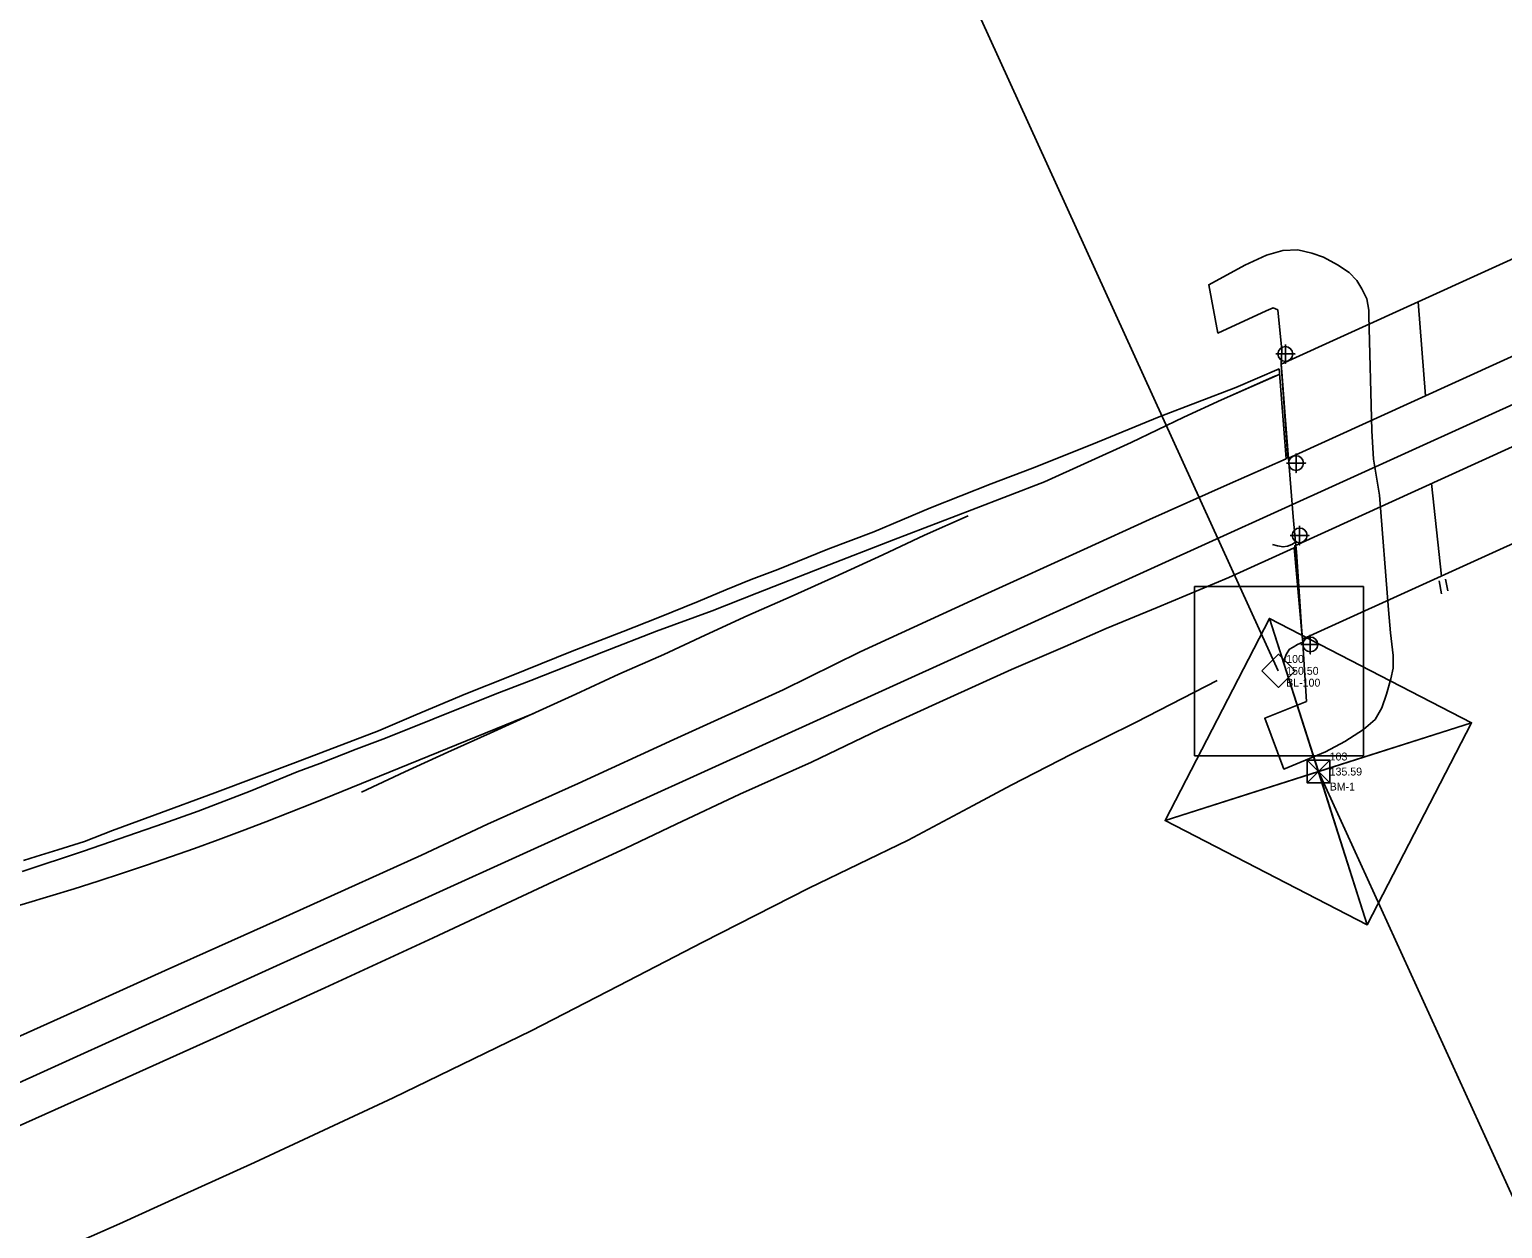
# Model space of a CAD drawing. Extents: x 2243531 to 2252747, y 658714 to 667210.
# Drawn here: x 2248509.1 to 2248974.4, y 663115.4 to 663494.4 of the extents above; entities that cross this region are included whole.
import ezdxf

# ---------------------------------------------------------------- set-up
doc = ezdxf.new("R2010")
doc.units = 0
for name, color, linetype in [('CTL Bench Mark CELL', 7, 'Continuous'), ('CTL Bench Mark Cogo Comment', 7, 'Continuous'), ('CTL Bench Mark Cogo Elevation', 7, 'Continuous'), ('CTL Bench Mark Cogo Number', 7, 'Continuous'), ('CTL NGS Horizontal CELL', 7, 'Continuous'), ('CTL Supplemental Horizontal and Vertical CELL', 7, 'Continuous'), ('CTL Supplemental Horizontal and Vertical Cogo Comment', 7, 'Continuous'), ('CTL Supplemental Horizontal and Vertical Cogo Elevation', 7, 'Continuous'), ('CTL Supplemental Horizontal and Vertical Cogo Number', 7, 'Continuous'), ('Exist DTM Regular Point CELL', 7, 'Continuous'), ('Exist Other Culture Area Outline', 7, 'Continuous'), ('Exist Roads Curbs', 7, 'Continuous'), ('Exist Roads EOP', 7, 'Continuous'), ('Exist Roads EOT', 7, 'Continuous'), ('Exist Structure Major Bridge Seam', 7, 'Continuous'), ('Exist Structure Major Bridge WW', 7, 'Continuous'), ('Exist Structure Major Deck Tunnel Box Culvert', 7, 'Continuous'), ('Prop Horizontal Alignment', 7, 'Continuous')]:
    doc.layers.add(name, color=color, linetype=linetype)

# ---------------------------------------------------------------- blocks, each defined once
blk = doc.blocks.new('CTL BENCH MARK')
at = {"layer": 'CTL Bench Mark CELL'}
blk.add_line((0, 0), (0, 0), dxfattribs=at)
blk.add_lwpolyline([(-0.072, 0.07175), (0.07175, 0.07175), (0.07175, -0.072), (-0.072, -0.072)], close=True, dxfattribs=at)
for points in [[(0.07175, 0.07175), (-0.072, -0.072), (-0.000125, -0.000125), (0.07175, -0.072), (-0.072, 0.07175)], [(-0.000125, -0.000125), (0.07175, 0.07175), (-0.072, 0.07175), (-0.000125, -0.000125)], [(-0.000125, -0.000125), (-0.072, -0.072), (0.07175, -0.072), (-0.000125, -0.000125)]]:
    blk.add_lwpolyline(points, dxfattribs=at)

msp = doc.modelspace()

# ---------------------------------------------------------------- linework, layer by layer
at = {"layer": 'CTL Bench Mark CELL'}
msp.add_line((2248916.28, 663259.84), (2248916.28, 663259.84), dxfattribs=at)
msp.add_line((2248916.28, 663259.84), (2248916.28, 663259.84), dxfattribs=at)
for points in [[(2248900.74, 663308.23), (2248964.61, 663275.27), (2248931.65, 663211.4), (2248867.78, 663244.36)], [(2248912.68, 663263.43), (2248919.87, 663263.43), (2248919.87, 663256.24), (2248912.68, 663256.24)]]:
    msp.add_lwpolyline(points, close=True, dxfattribs=at)
for points in [[(2248964.61, 663275.27), (2248867.78, 663244.36), (2248916.2, 663259.81), (2248931.65, 663211.4), (2248900.74, 663308.23)], [(2248916.2, 663259.81), (2248964.61, 663275.27), (2248900.74, 663308.23), (2248916.2, 663259.81)], [(2248916.2, 663259.81), (2248867.78, 663244.36), (2248931.65, 663211.4), (2248916.2, 663259.81)], [(2248919.87, 663263.43), (2248912.68, 663256.24), (2248916.27, 663259.83), (2248919.87, 663256.24), (2248912.68, 663263.43)], [(2248916.27, 663259.83), (2248919.87, 663263.43), (2248912.68, 663263.43), (2248916.27, 663259.83)], [(2248916.27, 663259.83), (2248912.68, 663256.24), (2248919.87, 663256.24), (2248916.27, 663259.83)]]:
    msp.add_lwpolyline(points, dxfattribs=at)
at = {"layer": 'CTL NGS Horizontal CELL'}
for p, q in [((2248903.54, 663291.68), (2248695.02, 663749.27)), ((2248916.28, 663259.84), (2249179.71, 662681.73))]:
    msp.add_line(p, q, dxfattribs=at)
at = {"layer": 'CTL Supplemental Horizontal and Vertical CELL'}
msp.add_line((2248903.54, 663291.68), (2248903.54, 663291.68), dxfattribs=at)
msp.add_line((2248903.54, 663291.68), (2248903.54, 663291.68), dxfattribs=at)
msp.add_line((2248903.54, 663291.68), (2248903.54, 663291.68), dxfattribs=at)
for points in [[(2248877.08, 663318.32), (2248930.45, 663318.32), (2248930.45, 663264.86), (2248877.08, 663264.86)], [(2248898.33, 663291.69), (2248903.57, 663296.94), (2248908.82, 663291.69), (2248903.58, 663286.44)], [(2248898.33, 663291.69), (2248903.57, 663296.94), (2248908.82, 663291.69), (2248903.58, 663286.44)]]:
    msp.add_lwpolyline(points, close=True, dxfattribs=at)
at = {"layer": 'Exist DTM Regular Point CELL'}
for points in [[(2248905.77, 663394.82), (2248905.77, 663388.82), (2248905.77, 663391.82), (2248908.77, 663391.82), (2248902.77, 663391.82)], [(2248909.15, 663360.33), (2248909.15, 663354.33), (2248909.15, 663357.33), (2248912.15, 663357.33), (2248906.15, 663357.33)], [(2248910.28, 663337.47), (2248910.28, 663331.47), (2248910.28, 663334.47), (2248913.28, 663334.47), (2248907.28, 663334.47)], [(2248913.64, 663303.01), (2248913.64, 663297.01), (2248913.64, 663300.01), (2248916.64, 663300.01), (2248910.64, 663300.01)]]:
    msp.add_lwpolyline(points, dxfattribs=at)
for centre in [(2248905.77, 663391.82), (2248909.15, 663357.33), (2248910.28, 663334.47), (2248913.64, 663300.01)]:
    msp.add_circle(centre, 2.34, dxfattribs=at)
at = {"layer": 'Exist Other Culture Area Outline'}
for points in [[(2248932.18, 663403.99), (2248932.14, 663405.62), (2248931.49, 663409.29), (2248929.9, 663412.43), (2248928.34, 663415.09), (2248925.9, 663417.6), (2248922.27, 663419.95), (2248917.85, 663422.38), (2248914.11, 663423.67), (2248909.76, 663424.73), (2248904.97, 663424.53), (2248899.8, 663423.06), (2248892.99, 663419.86), (2248881.57, 663413.68), (2248884.47, 663398.41), (2248899.76, 663405.47), (2248901.94, 663406.43), (2248903.35, 663405.81)], [(2248938.38, 663310.98), (2248935.46, 663347.18), (2248933.61, 663358.61), (2248933.11, 663367.48), (2248932.18, 663403.99)], [(2248954.34, 663320.17), (2248955.09, 663316.04)], [(2248956.31, 663320.64), (2248957.06, 663316.97)], [(2248912.46, 663281.95), (2248899.24, 663276.71), (2248905.32, 663260.64), (2248918.45, 663266.11), (2248924.52, 663269.35), (2248930.43, 663273.17), (2248934.13, 663276.29), (2248936.21, 663279.96), (2248937.74, 663284.28), (2248939.05, 663289.18), (2248939.87, 663292.53), (2248939.87, 663296.53), (2248938.96, 663303.71), (2248938.38, 663310.98)]]:
    msp.add_lwpolyline(points, dxfattribs=at)
at = {"layer": 'Exist Roads Curbs'}
for points in [[(2248909.02, 663332.34), (2248907.81, 663331.63), (2248906.43, 663331.04), (2248905.04, 663330.86), (2248903.25, 663331.16), (2248901.73, 663331.62)], [(2248911.26, 663300.74), (2248909.61, 663299.97), (2248908.19, 663299.14), (2248907.1, 663298.49), (2248906.1, 663297.04), (2248905.58, 663295.64), (2248905.55, 663294.41)]]:
    msp.add_lwpolyline(points, dxfattribs=at)
at = {"layer": 'Exist Roads EOP'}
for points in [[(2248903.84, 663387.13), (2248890.15, 663381.25), (2248865.93, 663371.91), (2248844.61, 663363.25), (2248825.94, 663355.73), (2248812.82, 663350.75), (2248793.66, 663343.19), (2248775.83, 663335.58), (2248761.3, 663330.1), (2248745.45, 663323.7), (2248737.08, 663320.59), (2248729.03, 663317.27), (2248720.32, 663313.59), (2248707.58, 663308.39), (2248696.57, 663304.12), (2248680.5, 663297.91), (2248660.69, 663289.91), (2248646.92, 663284.4), (2248631.11, 663277.8), (2248619.32, 663272.67), (2248593.07, 663262.71), (2248567.65, 663253.07), (2248548.74, 663246.18), (2248535.35, 663241.23), (2248526.44, 663237.77), (2248518.03, 663235.08), (2248511.19, 663233), (2248507.18, 663231.76)], [(2248903.84, 663387.13), (2248890.15, 663381.25), (2248865.93, 663371.91), (2248844.61, 663363.25), (2248825.94, 663355.73), (2248812.82, 663350.75), (2248793.66, 663343.19), (2248775.83, 663335.58), (2248761.3, 663330.1), (2248745.45, 663323.7), (2248737.08, 663320.59), (2248729.03, 663317.27), (2248720.32, 663313.59), (2248707.58, 663308.39), (2248696.57, 663304.12), (2248680.5, 663297.91), (2248660.69, 663289.91), (2248646.92, 663284.4), (2248631.11, 663277.8), (2248619.32, 663272.67), (2248593.07, 663262.71), (2248567.65, 663253.07), (2248548.74, 663246.18), (2248535.35, 663241.23), (2248526.44, 663237.77), (2248518.03, 663235.08), (2248511.19, 663233), (2248507.18, 663231.76)], [(2248903.84, 663387.13), (2248905.98, 663358.65)], [(2248905.98, 663358.65), (2248887.38, 663350.48), (2248862.86, 663339.47), (2248842.08, 663329.97), (2248810.66, 663315.72), (2248771.47, 663297.7), (2248747.19, 663285.65), (2248712.59, 663269.92), (2248682.42, 663256.06), (2248653.76, 663243.18), (2248632.91, 663233.39), (2248608.66, 663222.44), (2248587.98, 663213.08), (2248568.85, 663204.5), (2248551.96, 663197), (2248521.03, 663182.98), (2248482.04, 663165.45), (2248459.56, 663155.33), (2248440.59, 663146.88), (2248420.68, 663137.81), (2248395.93, 663126.99), (2248357.39, 663109.43)], [(2248908.51, 663330.5), (2248887.96, 663321.14), (2248865.23, 663311.73), (2248849.22, 663305.09), (2248836.2, 663299.39), (2248819.27, 663292.08), (2248797.73, 663282.31), (2248777.59, 663273.18), (2248756.1, 663262.8), (2248733.46, 663252.67), (2248713.31, 663243.21), (2248697.25, 663235.48), (2248674.61, 663225.11), (2248636.58, 663207.33), (2248602.37, 663191.53), (2248568.14, 663175.89), (2248533.29, 663160.21), (2248497.71, 663144.27), (2248461.34, 663127.8), (2248423.69, 663110.61)], [(2248911.05, 663302.42), (2248908.55, 663330.52)], [(2248514.52, 663106.74), (2248537.52, 663116.93), (2248556.69, 663125.67), (2248580.16, 663136.24), (2248623.94, 663156.69), (2248667.59, 663177.91), (2248695.08, 663192.1), (2248721.76, 663205.87), (2248755.26, 663222.95), (2248786.62, 663238.11), (2248807.14, 663249.1), (2248819.2, 663255.54), (2248838.17, 663265.36), (2248858.63, 663275.5), (2248884.24, 663288.67)], [(2248514.52, 663106.74), (2248537.52, 663116.93), (2248556.69, 663125.67), (2248580.16, 663136.24), (2248623.94, 663156.69), (2248667.59, 663177.91), (2248695.08, 663192.1), (2248721.76, 663205.87), (2248755.26, 663222.95), (2248786.62, 663238.11), (2248807.14, 663249.1), (2248819.2, 663255.54), (2248838.17, 663265.36), (2248858.63, 663275.5), (2248884.24, 663288.67)]]:
    msp.add_lwpolyline(points, dxfattribs=at)
at = {"layer": 'Exist Roads EOT'}
for points in [[(2248903.8, 663385.38), (2248885.65, 663377.3), (2248873.72, 663371.82), (2248857.08, 663363.84), (2248829.69, 663351.45), (2248806.74, 663342.52), (2248782.01, 663333.11), (2248759.76, 663324.45), (2248738.81, 663316.27), (2248724.76, 663310.68), (2248707.18, 663304.25), (2248690.36, 663297.67), (2248667.47, 663288.63), (2248656.13, 663284.28), (2248636.49, 663276.44), (2248621.54, 663270.37), (2248612.25, 663266.9), (2248600.82, 663262.41), (2248593.63, 663259.8), (2248578.78, 663253.6), (2248562.38, 663247.33), (2248551.42, 663243.38), (2248526.15, 663234.69), (2248506.74, 663228.27)], [(2248902.65, 663384.87), (2248885.65, 663377.3), (2248873.72, 663371.82), (2248857.08, 663363.84), (2248829.69, 663351.45), (2248806.74, 663342.52), (2248782.01, 663333.11), (2248759.76, 663324.45), (2248738.81, 663316.27), (2248724.76, 663310.68), (2248707.18, 663304.25), (2248690.36, 663297.67), (2248667.47, 663288.63), (2248656.13, 663284.28), (2248636.49, 663276.44), (2248621.54, 663270.37), (2248612.25, 663266.9), (2248600.82, 663262.41), (2248593.63, 663259.8), (2248578.78, 663253.6), (2248562.38, 663247.33), (2248551.42, 663243.38), (2248526.15, 663234.69), (2248506.74, 663228.27)], [(2248805.59, 663340.64), (2248791.78, 663334.55), (2248778.66, 663328.35), (2248763.51, 663321.43), (2248749.69, 663315.2), (2248736.02, 663309.15), (2248722.47, 663302.91), (2248709.47, 663296.86), (2248695.26, 663290.6), (2248681.66, 663284.31), (2248667.79, 663278), (2248654.57, 663272.02), (2248641.18, 663265.96), (2248627.6, 663259.76), (2248613.98, 663253.32)], [(2248805.59, 663340.64), (2248791.78, 663334.55), (2248778.66, 663328.35), (2248763.51, 663321.43), (2248749.69, 663315.2), (2248736.02, 663309.15), (2248722.47, 663302.91), (2248709.47, 663296.86), (2248695.26, 663290.6), (2248681.66, 663284.31), (2248667.79, 663278), (2248654.57, 663272.02), (2248641.18, 663265.96), (2248627.6, 663259.76), (2248613.98, 663253.32)]]:
    msp.add_lwpolyline(points, dxfattribs=at)
at = {"layer": 'Exist Structure Major Bridge Seam'}
for p, q in [((2248950.06, 663378.56), (2248947.73, 663408.27)), ((2248951.93, 663350.89), (2248955.05, 663321.61))]:
    msp.add_line(p, q, dxfattribs=at)
at = {"layer": 'Exist Structure Major Bridge WW'}
msp.add_lwpolyline([(2248912.46, 663281.95), (2248911.41, 663298.61), (2248911.26, 663300.74), (2248911.2, 663301.61), (2248911.02, 663304.05), (2248910.12, 663316.8), (2248909.24, 663329.28), (2248909.09, 663331.43), (2248909.02, 663332.34), (2248908.28, 663340.37), (2248906.73, 663358.94), (2248906.55, 663361.44), (2248905.64, 663373.53), (2248904.69, 663386.21), (2248904.48, 663388.64), (2248904.61, 663393.05), (2248903.35, 663405.81)], dxfattribs=at)
at = {"layer": 'Exist Structure Major Deck Tunnel Box Culvert'}
for points in [[(2248906.6, 663358.76), (2248904.48, 663388.56), (2249120.82, 663487.13), (2249123, 663457.36), (2248906.6, 663358.76)], [(2248911.14, 663301.65), (2248908.74, 663331.22), (2249125.33, 663429.85), (2249127.92, 663400.22), (2248911.14, 663301.65)]]:
    msp.add_lwpolyline(points, dxfattribs=at)
at = {"layer": 'Prop Horizontal Alignment'}
for p, q in [((2247500.8, 662705.02), (2249793.08, 663746.29)), ((2248668.27, 663278.18), (2248598.65, 663249.87))]:
    msp.add_line(p, q, dxfattribs=at)
msp.add_arc((2248237.01, 664139.15), 960, 261.59641, 292.13013, dxfattribs=at)

# ---------------------------------------------------------------- block references
at = {"layer": 'CTL Bench Mark CELL', "xscale": 50, "yscale": 50}
msp.add_blockref('CTL BENCH MARK', (2248916.28, 663259.84), dxfattribs=at)

# ---------------------------------------------------------------- texts
at = {"layer": 'CTL Bench Mark Cogo Comment'}
msp.add_text('BM-1', height=2.5, dxfattribs=at).set_placement((2248919.78, 663253.84))
at = {"layer": 'CTL Bench Mark Cogo Elevation'}
msp.add_text('135.59', height=2.5, dxfattribs=at).set_placement((2248919.78, 663258.59))
at = {"layer": 'CTL Bench Mark Cogo Number'}
msp.add_text('103', height=2.5, dxfattribs=at).set_placement((2248919.78, 663263.34))
at = {"layer": 'CTL Supplemental Horizontal and Vertical Cogo Comment'}
msp.add_text('BL-100', height=2.5, dxfattribs=at).set_placement((2248906.04, 663286.68))
msp.add_text('BL-100', height=2.5, dxfattribs=at).set_placement((2248906.04, 663286.68))
at = {"layer": 'CTL Supplemental Horizontal and Vertical Cogo Elevation'}
msp.add_text('150.50', height=2.5, dxfattribs=at).set_placement((2248906.04, 663290.43))
msp.add_text('150.50', height=2.5, dxfattribs=at).set_placement((2248906.04, 663290.43))
at = {"layer": 'CTL Supplemental Horizontal and Vertical Cogo Number'}
msp.add_text('100', height=2.5, dxfattribs=at).set_placement((2248906.04, 663294.18))
msp.add_text('100', height=2.5, dxfattribs=at).set_placement((2248906.04, 663294.18))

doc.saveas('drawing.dxf')
